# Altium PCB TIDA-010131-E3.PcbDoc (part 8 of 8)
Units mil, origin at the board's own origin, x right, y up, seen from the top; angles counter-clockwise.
Board outline 6889.76 x 5118.11 mil, 6 copper layers (Top Layer, GND Layer, Signal Layer 1, Signal Layer 2, PWR Layer, Bottom Layer), stack 58.5 mil thick; 758 components, 455 nets, 2194 pads, 1156 vias.
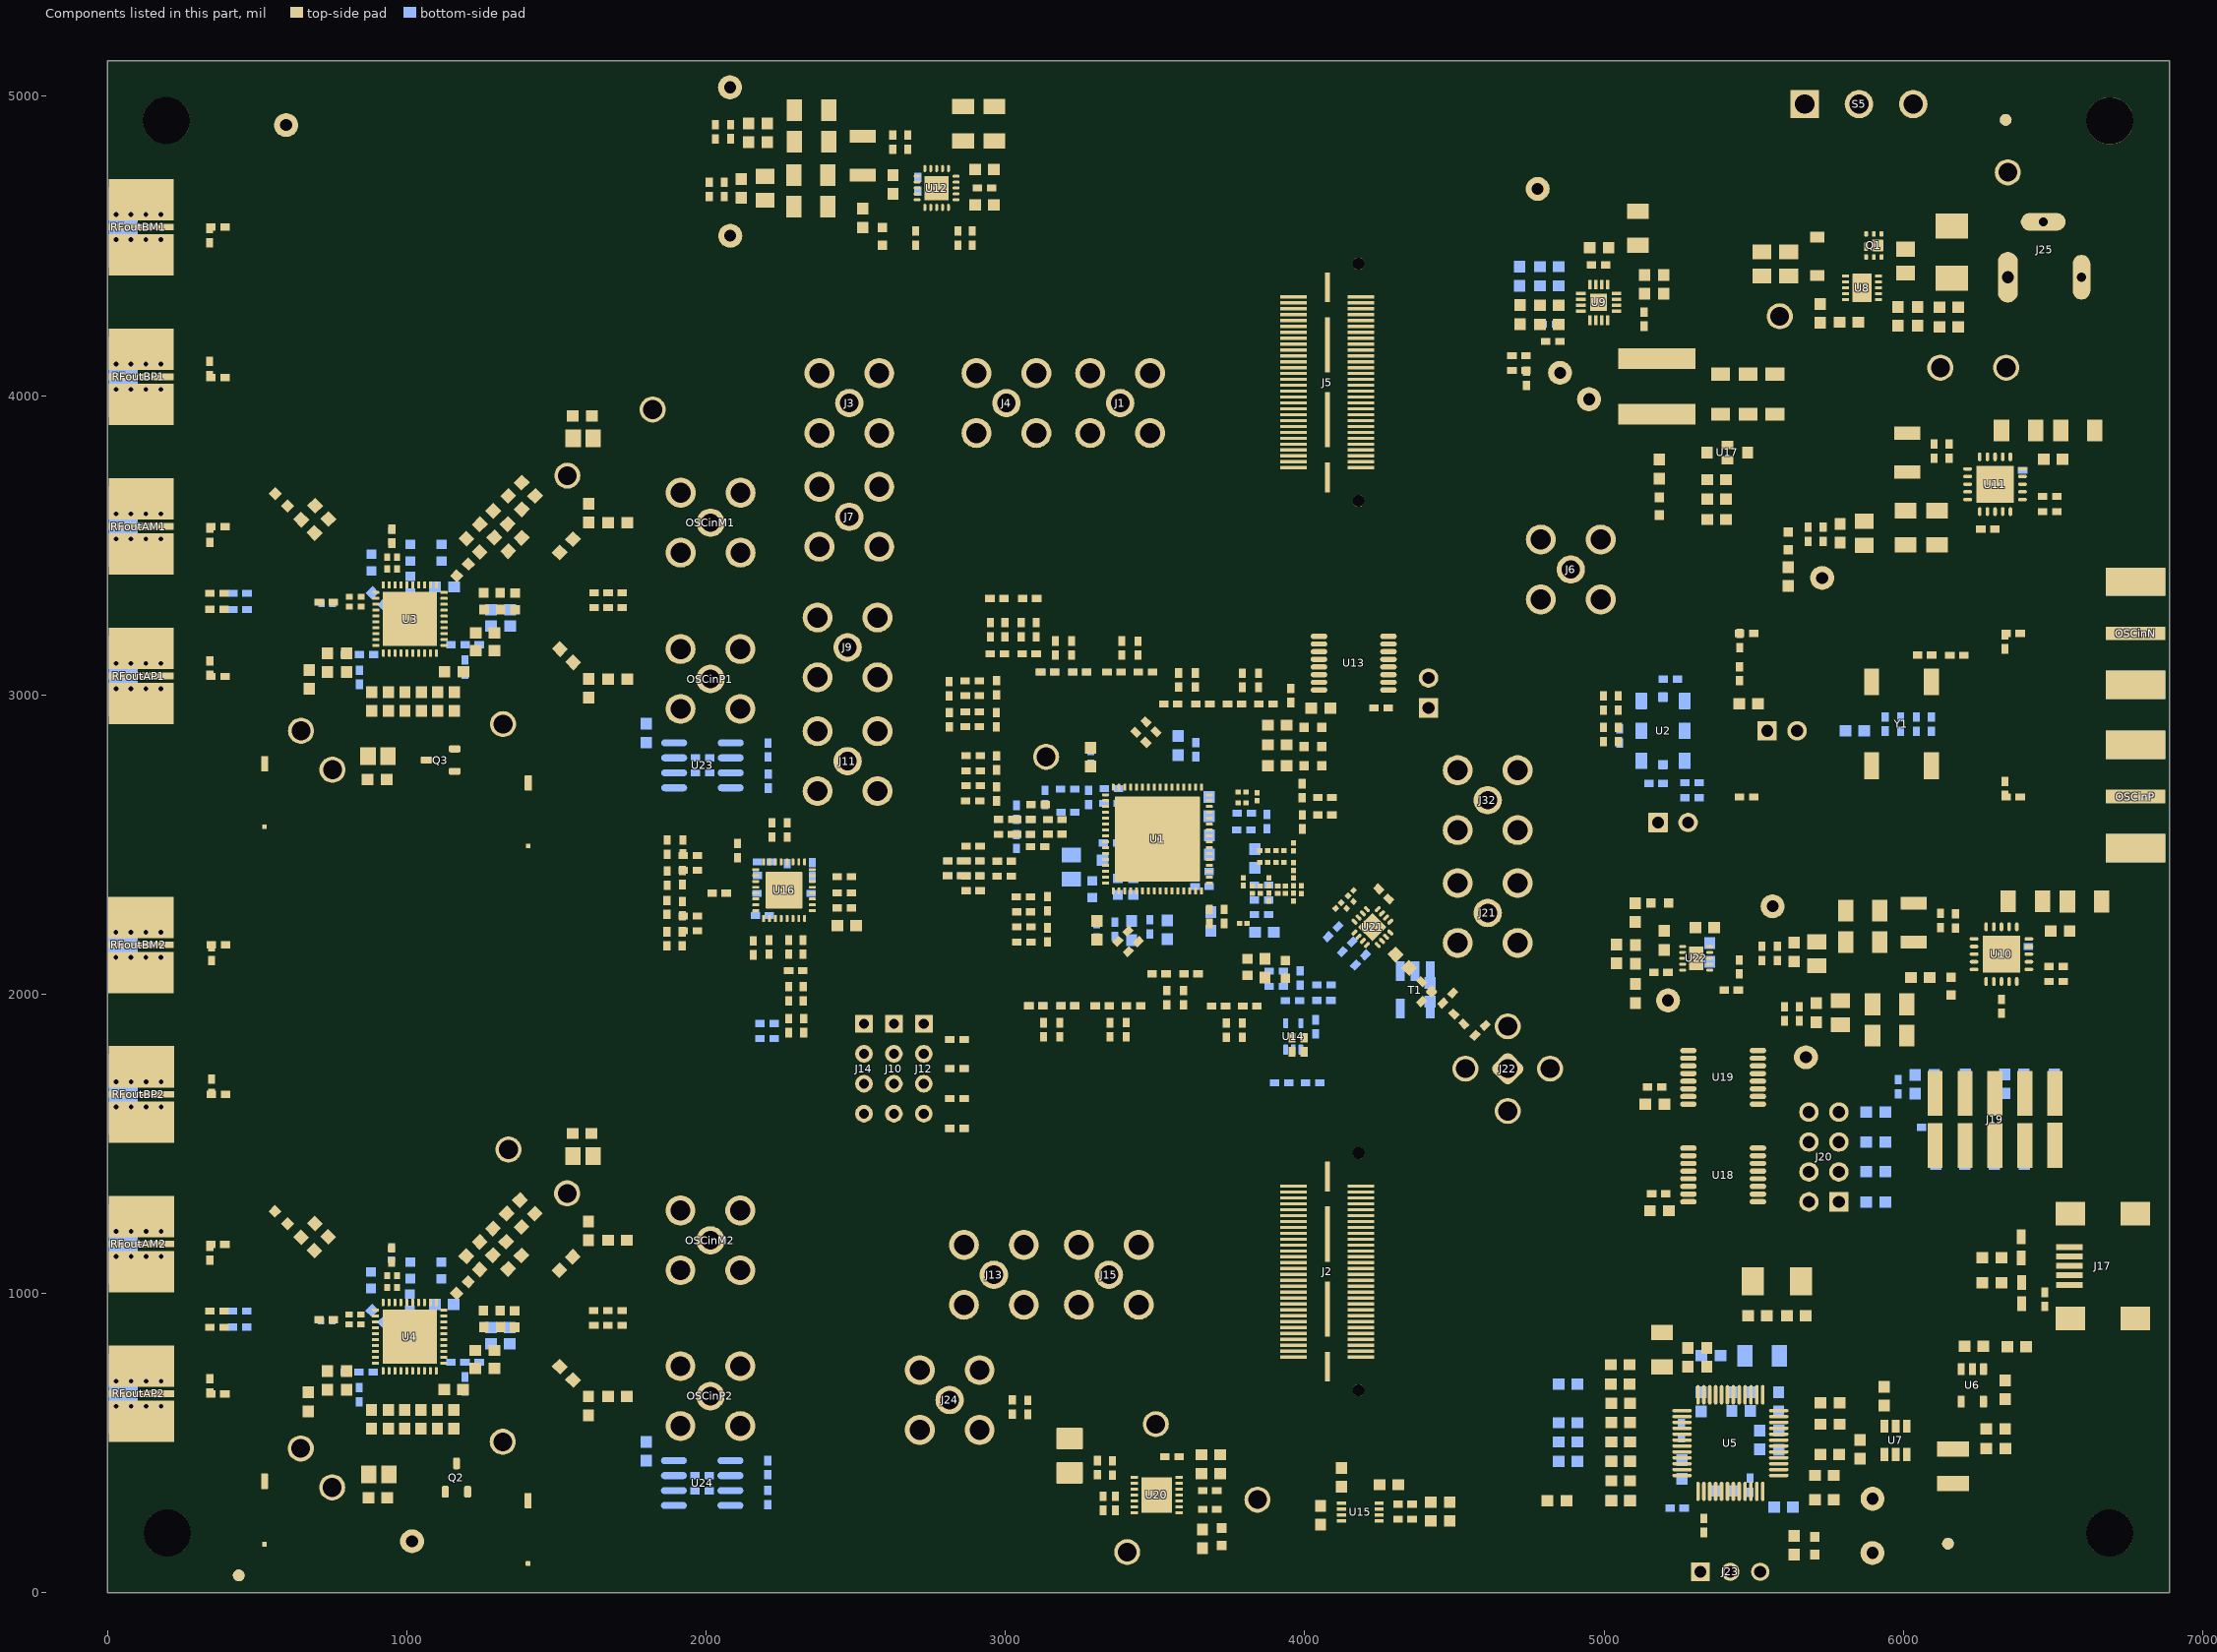
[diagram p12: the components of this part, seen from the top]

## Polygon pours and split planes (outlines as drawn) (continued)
no net on Top Solder "h" (solid): 378.94,634.26 2.41,634.26 -0.76,631.1 -0.76,697.1 6.02,690.32 379.46,690.32 508.41,690.32 619.48,801.39 657.18,839.1 678.24,839.1 695.24,856.1 775.24,856.1 798.24,856.1 828.24,886.1 831.61,889.46 831.61,942.65 808.82,965.43 685.15,965.43 639.96,1010.62 518.63,1131.95 380.29,1131.95 8.39,1131.95 -0.76,1141.1 -0.76,1202.55 6.13,1195.66 379.26,1195.66 539.68,1195.66 677.24,1058.1 712.24,1023.1 753.24,1023.1 785.92,1023.1 853.79,955.24 877.96,931.06 889.26,931.06 895.77,924.54 895.77,899.02 875.61,899.02 860.24,883.65 791.22,814.62 730,814.62 549.65,634.26 378.94,634.26
no net on Top Solder "h" (solid): 368.67,1121.97 368.67,1138.66 363.25,1144.08 296.82,1144.08 306,1134.89 306,1121.97 306,703.27 263.82,661.08 407.82,661.08 368.82,700.08 368.82,729.08 368.82,1124.11
no net on Top Solder "h" (solid): 369.43,3519.87 369.43,3536.57 364.01,3541.98 297.58,3541.98 306.76,3532.79 306.76,3519.87 306.76,3101.17 264.58,3058.98 408.58,3058.98 369.58,3097.98 369.58,3126.98 369.58,3522.01
no net on Top Solder "h" (solid): 379.7,3032.16 3.16,3032.16 0,3029 0,3095 6.77,3088.23 380.22,3088.23 509.17,3088.23 620.23,3199.3 657.94,3237 679,3237 696,3254 776,3254 799,3254 829,3284 832.37,3287.37 832.37,3340.55 809.58,3363.33 685.91,3363.33 640.72,3408.52 519.39,3529.85 381.05,3529.85 9.15,3529.85 0,3539 0,3600.45 6.89,3593.56 380.02,3593.56 540.44,3593.56 678,3456 713,3421 754,3421 786.68,3421 854.54,3353.14 878.72,3328.96 890.01,3328.96 896.53,3322.44 896.53,3296.92 876.37,3296.92 861,3281.55 791.97,3212.52 730.76,3212.52 550.4,3032.16 379.7,3032.16
no net on Top Solder "h" (solid): 368.85,4520.89 368.85,4537.59 363.44,4543 297,4543 306.19,4533.81 306.19,4520.89 306.19,4102.19 264,4060 408,4060 369,4099 369,4128 369,4523.03
no net on Top Solder "h" (solid): 10.56,4014.86 468.56,4014.86 528.82,4075.12 528.82,4356.56 541.31,4369.05 601.47,4369.05 619.48,4351.04 619.48,4095.52 681,4034 833.28,3881.72 833.28,3723.5 833.28,3443.64 872.62,3404.3 914.36,3404.64 934.9,3384.1 934.9,3369.91 969.01,3369.91 969.01,3391.01 982.64,3404.64 1003.74,3404.64 1027.76,3428.66 1056,3456.9 1056,3497.79 1073.04,3514.83 1073.03,4336.97 961,4449 803.88,4606.12 385.16,4606.12 5.67,4606.12 0.33,4600.78 0.33,4537.32 3.65,4534 202,4534 206,4538 298,4538 331,4538 360.82,4501.13 383.06,4523.37 766.14,4523.37 995.34,4294.17 995.34,3451.1 979.11,3434.87 923.38,3434.87 915,3443.25 915,3459 915,3486 909,3492 909,3918 820,4007 700,4127 700,4393 651.14,4441.86 476.89,4441.86 448.49,4413.45 448.49,4369.05 448.49,4112.15 426.17,4089.83 1.83,4089.83 1,4089 1,4045 1,4024.42
VDDD33 on Signal Layer 1 "12" (solid, remove dead copper, pour order 437): 5083,1904 4616,1437 4616,776 4479,639 3203,639 3100,536 3100,82 3147,35 6748,35 6828,115 6828,1702 6795,1735 5990,1735 5821,1904
GND on Signal Layer 1 "PWR Layer-No Net" (solid, remove dead copper, pour order 440): 4459.93,894.93 4254,689 3085,689 3009,613 3009,118 3009,58.5 2985.5,35 63.5,35 13,85.5 13,764 13,5011.5 77,5075.5 4320.5,5075.5 4458.16,4937.85
+3.3V_ALL on Signal Layer 1 "h" (solid, remove dead copper, pour order 411): 4685.5,5024 4615,5024 4546.5,4955.5 4514.5,4923.5 4514.5,4377.5 4514.5,2262.5 4841,1936 5843,1936 6014.5,1764.5 6630,1764.5 6799,1764.5 6831,1796.5 6831,4916 6723.49,5023.51
GND on Bottom Layer "h" (solid, remove dead copper, pour order 445): 282.85,35 63.5,35 25,73.5 25,5023.5 77,5075.5 6717,5075.5 6840.5,4952 6853.85,4938.65 6853.85,4240 6853.85,111 6777.85,35
GND on Bottom Layer "12" (solid, pour order 439): 4221,2266 4182,2227 4182,2222 4222,2182 4230,2182 4268,2220 4268,2229 4231,2266 4221,2266
5V on Bottom Layer "PWR Layer-No Net" (solid, remove dead copper, pour order 435): 5607,5053 5704,5053 5736,5021 5738,5019 5738,4938 5738,4731 6230,4239 6248,4239 6341,4239 6403,4177 6426,4154 6426,4063 6426,4043 6367,3984 6344,3961 6149,3961 6002,3961 5606,4357 5493,4470 5493,4731 5493,4959 5563,5029 5587,5053
NetJ25_1 on Bottom Layer "PWR Layer-No Net" (solid, remove dead copper, pour order 434): 5802,5038 5891,5038 5916,5013 5945,4984 5945,4913 5945,4811 6186,4570 6241,4515 6324,4515 6369,4515 6400,4484 6410,4474 6410,4399 6410,4305 6387,4282 6382,4277 6321,4277 6248,4277 5780,4745 5780,4902 5780,5016
GND on Signal Layer 2 "h" (solid, remove dead copper, pour order 441): 282.85,35 63.5,35 25,73.5 25,5023.5 77,5075.5 6717,5075.5 6840.5,4952 6853.85,4938.65 6853.85,4240 6853.85,111 6777.85,35
+2.5V on Signal Layer 2 "12" (solid, remove dead copper, pour order 438): 5085,2368 5430,2368 5459,2339 5467,2331 5467,2273 5467,1966 5437,1936 5032,1936 4991,1977 4991,2338 5021,2368
GND on GND Layer "h" (solid, remove dead copper, pour order 442): 282.85,35 63.5,35 25,73.5 25,5023.5 77,5075.5 6717,5075.5 6840.5,4952 6853.85,4938.65 6853.85,4240 6853.85,111 6777.85,35

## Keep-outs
Keep-Out Layer:
  lines w10: 6890.89,354.66 6890.89,4685.37 ; 0,0 6889.76,0 6889.76,5118.11 0,5118.11 0,0
  text ".Layer_Name" at -231.37,-1903.49 h60
Multi-Layer:
  circle w6: c4180.64,676.77 r30
  circle w6: c4180.64,1469.29 r30
  circle w6: c4180.64,3648.11 r30
  circle w6: c4180.64,4440.63 r30

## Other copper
Top Layer:
  pour cut-out: 6843.57,3263 6853.85,3252.72 6853.85,3152.85 6844,3143 6670,3143 6664,3149 6664,3258 6669,3263
  pour cut-out: 6843.57,2718 6853.85,2707.72 6853.85,2607.85 6844,2598 6670,2598 6664,2604 6664,2713 6669,2718
  pour cut-out: 4877,4394 4641,4394 4624,4377 4624,4175 4636,4163 4819,4163 4824,4168 4824,4188 4831,4195 4831,4162 4816.29,4147.29 4622.93,4147.29 4604.45,4165.77 4604.45,4385.38 4627.05,4407.99 4890.99,4407.99
  pour cut-out: 5384.39,3833.99 5384.39,3844.39 5393,3853 5394.61,3851.39 5432.61,3851.39 5432.61,3862.27 5371.96,3862.27 5371.96,3858.93 5370.64,3857.61
  region net GND: 4234,2279 4234,2290 4323,2379 4331,2379 4349,2361 4349,2355 4283,2289 4283,2283 4283,2259 4263,2239 4263,2232 4268,2227 4268,2221 4233,2186 4223,2186 4185,2224 4185,2230
  pour cut-out: 1076.07,752.75 1092.25,752.75 1096,749 1096,732 1091.39,727.4 1072.32,727.4 1070,729.72 1070,746.68
  text "TOP LAYER" at -232.15,-1885 h60
GND Layer:
  text "GND Layer" at -205,-1900 h60
Signal Layer 2:
  text "Signal Layer2" at -215,-1900 h60
Signal Layer 1:
  text "Signal Layer1" at -225,-1890 h60
PWR Layer:
  text "PWR Layer" at -195,-1890 h60
Bottom Layer:
  text "BOTTOM LAYER" at -231.37,-1903.49 h60

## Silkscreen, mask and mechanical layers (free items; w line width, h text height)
Top Overlay:
  drawing of 487 lines, arcs and shapes, not listed
  text "+3.3V_LMXRF" at 1694.68,4987.01 h30
  text "GND" at 560.11,4794.49 h30
  text "PGND" at 6455,4709 h30
  text "TIDA-010131-E3" at 3278.18,4651.02 h80
  text "+3.3V_LMX" at 1911.74,4434.15 h30
  text "5VIN" at 5675.09,4093.58 h30 r90
  text "5V" at 6437,4023 h30
  text "EN" at 6016.56,4007.17 h30
  text "B" at 3455,3636 h30
  text "A" at 3096,3619 h30
  text "+3.3V_VCO" at 5788.76,3350 h30
  text "+3.3V_VCO" at 5203.22,2645.43 h30 r90
  text "CLKINN" at 4781.86,2592.14 h30
  text "+3.3V_VCO" at 5573.22,2559.43 h30 r90
  text "A" at 2904,2552 h30
  text "C" at 3762.83,2444.56 h40
  text "B" at 2730,2427 h30
  text "+3.3V_LMK" at 5485.43,2406.78 h30
  text "+2.5v" at 5153,2389 h30
  text "CLKINP" at 4779.47,2205.12 h30
  text "VDD33" at 5618,1688.68 h30
  text "LMK_CLKIN" at 4792,1535 h30 r45
  text "C" at 4393,1443 h40
  text "VDD33" at 5397,139 h30 r90
  text "V_BUS" at 5552,130 h30 r90
  text "VREGIN" at 5445,129 h30 r90
  text "GND" at 873.48,125 h30
  text "GND" at 5977,90 h30
  text "TOP OVERLAY" at -231.37,-1903.49 h50
Bottom Overlay:
  lines w6: 838.89,949.64 849.89,938.64 852.89,938.64 ; 949.65,3440.55 967.65,3458.55 983.65,3458.55 ; 1214.74,687.74 1214.74,698.1 ; 1985.35,276.78 1985.35,307.06 ; 1986.27,229.7 1986.27,251.14 ; 1988.81,2677.47 1988.81,2707.75 ; 1989.73,2630.4 1989.73,2651.84 ; 2095.32,2306.91 2136.32,2306.91 2145.82,2316.41 ; 2112.32,2386.91 2141.32,2386.91 ; 2291.32,2459.91 2297.32,2465.91 ; 2375.82,2316.41 2386.32,2305.91 2388.32,2305.91 ; 2901,2286 2901,2311 ; 2945.72,2554.28 3012.78,2554.28 ; 2946,2605 3008.16,2605 3013.16,2600 ; 3104.58,2713.76 3109.64,2708.71 ; 3200,2834 3200,2790.03 3250,2740.03 3250,2714 ; 3297.17,2469.08 3297.17,2472.3 ; 3407.24,2623.19 3439.39,2623.19 3454.6,2638.4 3454.6,2664.68 ; 3559.97,2374.66 3560.97,2375.66 3560.97,2391.66 3577.97,2408.66 3606.97,2408.66 ; 3708.84,2464.78 3724.85,2464.78 3735.02,2464.78 ; 3799.97,2042.66 3803.76,2046.44 3857.03,2046.44 ; 3800.86,2637.97 3800.86,2660.67 ; 3865.97,1985.66 3866.97,1986.66 3908.97,1986.66 ; 3903.57,2286.28 3939.59,2286.28 ; 3903.57,2335.28 3936.44,2335.28 3940.94,2330.78 ; 4024,1834 4024,1821 4030,1815 ; 4161.74,2206.73 4161.74,2213.74 4167,2219 ; 4886.59,4420.6 4902.29,4404.9 4923.23,4404.9 ; 5392.11,561.18 5392.11,569.24 5399.08,576.22 ; 5516.47,699 5529.5,712.04 ; 5583.06,422.64 5583.06,441.51 ; 5618.18,691.01 5641.55,691.01 ; 5951,1373 5951,1365 5953,1363 5967,1363 ; 5967.98,1478.8 5979.78,1467 5991,1467 ; 6048,1823 6066.27,1804.73 6066.27,1758.98 ; 1985.35,307.06 1992.51,299.9 1977.9,299.9 1985.06,307.06 1985.35,307.06 ; 1986.27,251.14 1993.01,244.4 1980.25,244.4 1986.27,250.43 1986.27,251.14 ; 1988.81,2707.75 1988.51,2707.75 1981.35,2700.6 1995.96,2700.6 1988.81,2707.75 ; 1989.73,2651.84 1989.73,2651.12 1983.71,2645.1 1996.47,2645.1 1989.73,2651.84 ; 2901,2311 2902,2311 2908,2305 2895,2305 2901,2311 ; 3800.86,2660.67 3795.09,2654.91 3794.84,2654.91 3806.62,2654.91 3800.86,2660.67
  text "BOTTOM OVERLAY" at -117.15,-1917 h50
Top Paste:
  text "TOP PASTE" at -231.37,-1903.49 h60
Bottom Paste:
  text "BOTTOM PASTE" at -231.37,-1903.49 h60
Top Solder:
  text "TOP SOLDER" at -231.37,-1903.49 h60
Bottom Solder:
  text "BOTTOM SOLDER" at -231.37,-1903.49 h60
Drill Guide:
  text ".Layer_Name" at -231.37,-1903.49 h60
M1 Board Outline:
  the board outline again, w10
M2 Board Dimensions:
  rectangle: -683.87,-1455.5 -308.87,-1330.5
  rectangle: -808.87,-1330.5 -683.87,-1205.5
  lines w7: -808.87,-1330.5 191.13,-1330.5 ; -683.87,-1455.5 -683.87,-1205.5 ; -558.87,-1455.5 -558.87,-1205.5 ; -308.87,-1455.5 -308.87,-1205.5 ; -58.87,-1455.5 -58.87,-1205.5 ; -808.87,-1455.5 -808.87,-1205.5 191.13,-1205.5 191.13,-1455.5 -808.87,-1455.5
  lines w10: -808.87,-1520.5 -808.87,-1500.5 ; -748.87,-1530.5 -808.87,-1510.5 ; -748.87,-1490.5 -808.87,-1510.5 ; -584.79,-1510.5 -808.87,-1510.5 ; -32.95,-1510.5 191.13,-1510.5 ; 131.13,-1530.5 191.13,-1510.5 ; 131.13,-1490.5 191.13,-1510.5 ; 191.13,-1520.5 191.13,-1500.5
  text "1000 (mil)" at -574.79,-1546.49 h60
M3 3D STEP Top:
  text ".Layer_Name" at -231.37,-1903.49 h60
M4 3D STEP Bottom:
  text ".Layer_Name" at -231.37,-1903.49 h60
M5 Assembly Top:
  circle w10: c6093.33,3037.38 r21.33
  circle w10: c5501.31,3811.99 r14.18
  circle w10: c5544.19,2882.66 r23.65
  circle w10: c2522.41,1903.14 r14.87
  circle w10: c2627.47,1901.66 r14.87
  circle w10: c2725.47,1902.66 r14.87
  circle w10: c4410.97,2960.66 r16.49
  circle w10: c6548.35,1029.45 r11.18
  circle w10: c6753.97,3206.66 r13.42
  circle w10: c6762.97,2655.66 r13.42
  circle w10: c6509,1669 r11.18
  circle w10: c6288,749 r2.83
  circle w6: c1129,317 r8.25
  circle w6: c5119,137 r18.03
  circle w6: c5318,83 r19.92
  circle w6: c5656,4989 r12.65
  lines w6: 1838.32,2288.91 1815.32,2288.91 ; 1838.32,2386.91 1815.32,2386.91 ; 3889,2504 3889,2516 3837,2516 3837,2597 3837,2608 3946,2608 3946,2531 3937,2522 3937,2504 ; 3917,2502 3917,2520 ; 3921,2413 3758,2413 3758,2320 3800,2278 4022,2278 4152,2408 4471,2408 4471,2549 4389,2631 4376,2631 ; 3994,2399 4058,2399 4099,2440 4099,2543 4187,2631 4390,2631 ; 4078,2171 4078,2231 4095,2248 ; 4095,2240 4095,2248 ; 4142,2438 4066,2362 4034,2362 4020,2362 ; 4161,2389 4162,2389 4226,2325 4219,2318 4122,2221 4228,2115 4228,2079 4080,1931 3974,2037 3974,2082 4053,2161 4053,2281 4161.5,2389.5 ; 5239.21,2051.35 5246.56,2044 5255,2044 ; 1815.32,2288.91 1821.32,2282.91 1821.32,2294.91 1815.32,2288.91 ; 1815.32,2386.91 1821.32,2392.91 1821.32,2380.91 1815.32,2386.91 ; 3917,2520 3911,2514 3925,2514 3919,2520 3917,2520 ; 4020,2362 4027,2369 4027,2356 4021,2362 4020,2362 ; 4095,2248 4085,2248 4094,2239 4094,2247 4095,2248 ; 6520.28,945.38 6522.28,943.38 6888.28,943.38 6888.28,1245.38 6520.28,1245.38 6520.28,964.96 6520.28,945.38
  lines w10: -1100.37,-1975.17 5499.63,-1975.17 ; -1100.37,-1771.83 5501.63,-1771.83 ; -1100.37,-1568.5 -1100.37,-2178.5 2904.63,-2178.5 5501.63,-2178.5 5501.63,-1568.5 -1099.87,-1568.5 -1099.87,-2178.5 475.63,-2178.5 ; 1364.63,-2178.5 1364.63,-1568.5 ; 2631.63,-1771.83 2631.63,-1568.5 ; 3471.63,-1771.83 3471.63,-1568.5 ; 4093.63,-2185 4093.63,-1982.17
  text "2" at 4167.79,4327.1 h25
  text "1" at 3968.34,4322.43 h25
  text "59" at 3964.56,3749.53 h25
  text "60" at 4150.43,3749.53 h25
  text "1" at 3963.74,1351.19 h25
  text "2" at 4163.53,1349.9 h25
  text "J24" at 6676.38,1016.28 h25
  text "60" at 4146.04,778.64 h25
  text "59" at 3964.28,774.68 h25
  text "U5" at 5405,481 h25
  text "COMPONENTS MARKED 'DNP' SHOULD NOT BE POPULATED." at 345.13,-1363.5 h25
  text "ASSEMBLY VARIANT:" at 344.63,-1479 h25
  text ".VariantName" at 1380.63,-1479 h25
  text "E3" at 3066.85,-1694 h25
  text "PCB VIEWED FROM TOP SIDE" at -1036.87,-1700.67 h25
  text "BOARD #:" at 1439.63,-1700.67 h25
  text "'.PRJ_Number'" at 1985.13,-1700.67 h25
  text "REV:" at 2829.63,-1700.67 h25
  text "SVN REV:" at 3667.63,-1700.67 h25
  text "010131" at 1760.73,-1895.8 h25
  text "ASSEMBLY TOP" at -225.15,-1898 h25
  text "TID #:" at 1421.89,-1901.13 h25
  text "IGNORE ->" at -1036.87,-1903.49 h25
  text "PLOT NAME =" at -1036.87,-2109.34 h25
  text ".plot_File_Name" at -231.37,-2109.34 h25
  text "GENERATED    :" at 1441.63,-2109.34 h25
  text "'.Print_Date'" at 2311.13,-2109.34 h25
  text "'.Print_Time'" at 3040.13,-2109.34 h25
  text "TEXAS INSTRUMENTS" at 4304.63,-2109.34 h25
M6 Assembly Bottom:
  circle w10: c2094.32,442.14 r10.94
  circle w10: c2099.72,2839.25 r11.5
  circle w10: c3986.13,1797.87 r5.36
  lines w6: 3250,2733 3271,2712 3271,2709 ; 1847.69,2665.26 2128.74,2665.26 2128.74,2863.47 2127.7,2864.51 2024.37,2864.51 1847.69,2864.51 1847.69,2665.26 ; 1848.36,267.88 1848.36,467.13 2025.04,467.13 2128.36,467.13 2129.4,466.09 2129.4,267.88 1848.36,267.88
  lines w10: -1100.87,-1772.33 5501.13,-1772.33 ; -1098.87,-1975.67 5501.13,-1975.67 ; 307.13,-2185.5 307.13,-1982.67 ; 929.13,-1772.33 929.13,-1569 ; 1769.13,-1772.33 1769.13,-1569 ; 3036.13,-2179 3036.13,-1569 ; 3925.13,-2179 5500.63,-2179 5500.63,-1569 -1100.87,-1569 -1100.87,-2179 1496.13,-2179 5501.13,-2179 5501.13,-1569
  text "COMPONENTS MARKED 'DNP' SHOULD NOT BE POPULATED." at 5293.63,-1363 h25
  text ".VariantName" at 4249.63,-1479 h25
  text "ASSEMBLY VARIANT:" at 5288.63,-1479 h25
  text "E3" at 1297.23,-1687.14 h25
  text "SVN REV:" at 733.13,-1701.17 h25
  text "REV:" at 1571.13,-1701.17 h25
  text "'.PRJ_Number'" at 2415.63,-1701.17 h25
  text "BOARD #:" at 2961.13,-1701.17 h25
  text "PCB VIEWED FROM BOTTOM SIDE" at 5437.63,-1701.17 h25
  text "ASSEMBLY BOTTOM" at 4320.69,-1890.28 h25
  text "010131" at 2635.44,-1893.21 h25
  text "TID #:" at 2974.28,-1898.54 h25
  text "IGNORE ->" at 1739.48,-1903.49 h25
  text "LAYER NAME =" at 5364.94,-1902.63 h25
  text "TEXAS INSTRUMENTS" at 96.13,-2109.84 h25
  text "'.Print_Time'" at 1360.63,-2109.84 h25
  text "'.Print_Date'" at 2089.63,-2109.84 h25
  text "GENERATED    :" at 2959.13,-2109.84 h25
  text ".plot_File_Name" at 4632.13,-2109.84 h25
  text "PLOT NAME =" at 5437.63,-2109.84 h25
M9 Title Sheet:
  drawing of 58 lines, arcs and shapes, not listed
  text "1" at -68.53,6991.5 h70
  text "2" at 2427.13,6991.5 h70
  text "3" at 4916.47,6991.5 h70
  text "4" at 7423.14,6991.5 h70
  text "5" at 9922.13,6991.5 h70
  text "6" at 12427.13,6991.5 h70
  text "A" at 16796.85,5852 h70
  text "A" at -1224.87,5848.5 h70
  text "B" at 16796.85,3472 h70
  text "B" at -1224.87,3468.5 h70
  text "C" at 16796.85,1097 h70
  text "C" at -1224.87,1093.5 h70
  text ".PRJ_Title" at 13806.85,-897.33 h70
  text "DESIGNED FOR:" at 13756.85,-1065 h45
  text ".PRJ_Customer" at 13806.85,-1205 h70
  text "D" at 16796.85,-1273 h70
  text "D" at -1224.87,-1276.5 h70
  text "FILE NAME:" at 13756.85,-1365 h45
  text ".PCB_File_Name_No_Path" at 13806.85,-1485 h70
  text "Texas Instruments (TI) and/or its licensors do not warrant the accuracy or completeness of this specification" at 5565.63,-1650.34 h45
  text "ENGINEER:" at 13756.85,-1655 h45
  text "LAYOUT BY:" at 15261.85,-1655 h45
  text "or any information contained therein. TI and/or its licensors do not warrant that this design will meet" at 5520.65,-1763 h45
  text ".PRJ_Engineer" at 13806.85,-1809.99 h70
  text ".PCB_Layout" at 15312.35,-1809.99 h70
  text "the specifications, will be suitable for your application or fit for any particular purpose, or will operate in" at 5520.65,-1875.67 h45
  text "ALTIUM DESIGNER VERSION:" at 15261.85,-1965 h45
  text "an implementation. TI and/or its licensors do not warrant that the design is production worthy. You should" at 5520.65,-1988.33 h45
  text ".print_Scale" at 13806.85,-2098.33 h70
  text ".Application_BuildNumber" at 15312.35,-2098.33 h70
  text "completely validate and test your design implementation to confirm the system functionality for your application." at 5565.63,-2101 h45
  text "1" at -68.53,-2308.5 h70
  text "2" at 2427.13,-2308.5 h70
  text "3" at 4916.47,-2308.5 h70
  text "4" at 7423.14,-2308.5 h70
  text "5" at 9922.13,-2308.5 h70
  text "6" at 12427.13,-2308.5 h70
M10 Fab Notes:
  drawing of 245 lines, arcs and shapes, not listed
  text "DESIGN INFORMATION" at 14794.37,5768.5 h60
  text "(REFER ALSO ARRAY/PANEL PROFILING INFORMATION)" at 14432.81,5606.79 h60
  text "BOARD SIZE" at 13746.81,5602.5 h60
  text "130mm" at 14894.57,5478.5 h60
  text "X" at 14714.81,5474.68 h60
  text "175MM" at 14149.57,5468.5 h60
  text "Number of Layers :" at 14149.81,5277.5 h60
  text "6" at 15244.62,5267.5 h60
  text "MIN. TRACK WIDTH:" at 14149.81,5138.5 h60
  text "MIL" at 15400.81,5138.5 h60
  text "4.25" at 15137.57,5137.5 h60
  text "4.25" at 15122.57,5010.5 h60
  text "MIN. CLEARANCE:" at 14149.81,5006.5 h60
  text "MIL" at 15400.81,5006.5 h60
  text "16" at 15189,4882 h60
  text "MIN. VIA PAD SIZE:" at 14149.81,4874.5 h60
  text "MIL" at 15400.81,4874.5 h60
  text "5.90 MIL" at 14844.81,4732.79 h60
  text "MINIMUM ANNULAR RING" at 13820.58,4728.5 h60
  text "EXTERNAL" at 15657.57,4728.5 h60
  text "PER" at 14020.58,4610.5 h60
  text "IPC-D-275 CLASS 2 LEVEL C" at 14240.58,4610.5 h60
  text "+/-" at 15336.35,4497.5 h60
  text "MIL, HOLES" at 15728.81,4498.21 h60
  text "+/-" at 16190.35,4497.5 h60
  text "5" at 15596.55,4492.5 h60
  text "3" at 16429.55,4492.5 h60
  text "REGISTRATION TOLERANCES:" at 13820.58,4492.5 h60
  text "METAL" at 15020.35,4492.5 h60
  text "MIL" at 16545.81,4492.5 h60
  text "IMPEDANCE TABLE:-" at 7654.85,4374 h60
  text "MATERIAL:" at 13745.81,4283.04 h60
  text "SE IMP" at 8220.85,4206 h50
  text "SE TRACE" at 8617.85,4203 h50
  text "DIFF TRACE" at 9540.85,4203 h50
  text "DIFF IMP" at 9093.85,4202 h50
  text "DIFF IMP" at 10286.85,4202 h50
  text "Rogers4003C and FR4 370" at 15975,4160 h30
  text "FR-4 High Tg" at 14732.25,4142.71 h60
  text "REFERENCE" at 11558.85,4139 h50
  text "X" at 15465,4135 h60
  text "FR-408" at 14166.81,4134.14 h60
  text "OTHER" at 15654.81,4134.14 h60
  text "(OHM)" at 8255.85,4118 h50
  text "(OHM)" at 9128.85,4114 h50
  text "(OHM)" at 10321.85,4114 h50
  text "WIDTH IN" at 8625.85,4108 h50
  text "WIDTH/SPACING" at 9548.85,4108 h50
  text "WIDTH/SPACING" at 10741.85,4108 h50
  text "Layer" at 7752.85,4089 h50
  text "+/-10%" at 8234.85,4034 h50
  text "Layer" at 11641.85,4032 h50
  text "+/-10%" at 9107.85,4030 h50
  text "+/-10%" at 10300.85,4030 h50
  text "MILS" at 8625.85,4021 h50
  text "IN MILS" at 9548.85,4021 h50
  text "IN MILS" at 10741.85,4021 h50
  text "63 MIL (1.6mm) +/-10%" at 14486.91,3971.42 h60
  text "THICKNESS:" at 13820.58,3967.14 h60
  text "X" at 14358.75,3967.14 h60
  text "OTHER" at 15771.81,3967.14 h60
  text "50(CPW)" at 8223.85,3877 h50
  text "22mil" at 8653.85,3875 h50
  text "15mil trace/" at 9581.85,3871 h50
  text "12mil trace/" at 10790.85,3869 h50
  text "GND" at 11640.85,3862 h50
  text "90 ohms" at 9101.85,3827 h50
  text "100 ohms" at 10281.85,3825 h50
  text "Top Layer" at 7702.85,3818 h50
  text "TOLERANCE:" at 13820.58,3809.14 h60
  text "X" at 14659.88,3809.14 h60
  text "ANSI IPC-6012 TYPE 3 CLASS 2" at 14846.83,3809.14 h60
  text "24mil" at 8653.85,3785 h50
  text "7mil space" at 9581.85,3785 h50
  text "Layer" at 11644.85,3784 h50
  text "8mil space" at 10790.85,3783 h50
  text "50" at 8223.85,3781 h50
  text "OTHER +/-" at 14846.81,3653.14 h60
  text "5.5mil trace/" at 10796.85,3648 h50
  text "SIGNAL" at 7769.85,3634 h50
  text "GND" at 11635.85,3623 h50
  text "100 ohms" at 10297.85,3616 h50
  text "90 ohms" at 9105.85,3611 h50
  text "10.5 mil" at 8649.85,3607 h50
  text "50" at 8330.85,3602 h50
  text "-" at 9780,3580 h60
  text "6mil space" at 10796.85,3562 h50
  text "Layer1" at 7782.85,3555 h50
  text "Layer" at 11639.85,3545 h50
  text "BOW & TWIST:" at 13820.58,3496.14 h60
  text "X" at 14659.88,3496.14 h60
  text "ANSI IPC-6012 TYPE 3 CLASS 2" at 14846.83,3496.14 h60
  text "5.5mil trace/" at 10788.85,3415 h50
  text "SIGNAL" at 7769.85,3407 h50
  text "PWR" at 11633.85,3393 h50
  text "10.5 mil" at 8643.85,3379 h50
  text "50" at 8322.85,3377 h50
  text "100 ohms" at 10289.85,3377 h50
  text "90 ohms" at 9095.85,3376 h50
  text "-" at 9780,3365 h60
  text "OTHER +/-" at 14846.81,3337.63 h60
  text "6mil space" at 10788.85,3329 h50
  text "Layer2" at 7782.85,3328 h50
  text "Layer" at 11637.85,3315 h50
  text "COPPER THICKNESS (FINISHED):" at 13745.81,3202.14 h60
  text "BOTTOM" at 7768.85,3181 h50
  text "PWR" at 11638.85,3177 h50
  text "4.25mil trace/" at 10733.85,3172 h50
  text "13.5 mil" at 8649.85,3141 h50
  text "90 ohms" at 9092.85,3126 h50
  text "100 ohms" at 10294.85,3122 h50
  text "-" at 9775,3120 h60
  text "50" at 8333.85,3113 h50
  text "Layer" at 7781.85,3102 h50
  text "Layer" at 11642.85,3099 h50
  text "4.25mil space" at 10733.85,3086 h50
  text "1.4MIL (1oz)" at 14625.81,3049.42 h60
  text "2MIL (1.4oz)" at 15392.81,3049.42 h60
  text "2.8MIL (2oz)" at 16119.81,3049.42 h60
  text "OUTER:" at 14102.81,3045.14 h60
  text "X" at 14497.35,3044.5 h60
  text "X" at 15267.35,2895.5 h60
  text "N/A" at 16119.35,2892.79 h60
  text "1.4MIL (1oz)" at 14625.81,2892.42 h60
  text "0.7MIL (1/2oz)" at 15392.81,2892.42 h60
  text "INNER SIGNAL:" at 13813.73,2888.14 h60
  text "X" at 14497.35,2884.5 h60
  text "22 mil (CPW) width on top layer should be controlled 50 ohms +/- 5%" at 7567,2816 h60
  text "DRILLING:" at 13745.81,2749.14 h60
  text "ALL SMA CONNECTORS TO FLUSH TO THE EDGE OF THE BOARD, NO GAP ALLOWED." at 7635,2687 h60
  text "REFERENCE:" at 13820.58,2632.14 h60
  text "X" at 14468.81,2632.14 h60
  text "AS SHOWN" at 14655.81,2632.14 h60
  text "X" at 15369.81,2632.14 h60
  text "NC_DRILL FILES" at 15506.81,2632.14 h60
  text "This is especially critical for:  RFoutAP, RFoutAM, RFoutBP, and RFoutBM SMA connectors" at 7622,2572 h60
  text "PTH MIN COPPER THICKNESS:" at 13820.58,2474.14 h60
  text "X" at 15170.81,2474.14 h60
  text "1MIL" at 15307.81,2474.14 h60
  text "OTHER" at 15804.81,2474.14 h60
  text "BOARD FINISH:" at 13745.81,2315.14 h60
  text "SILKSCREEN:" at 13901.03,2197.14 h60
  text "X" at 14849.81,2197.14 h60
  text "TOP" at 14975.81,2197.14 h60
  text "X" at 15359.81,2197.14 h60
  text "BOTTOM" at 15486.81,2197.14 h60
  text "SILKSCREEN COLOR:" at 13901.03,2030.14 h60
  text "X" at 14848.77,2030.14 h60
  text "WHITE" at 14975.81,2030.14 h60
  text "OTHER" at 15486.81,2030.14 h60
  text "SOLDER RESIST COLOR:" at 13901.03,1860.14 h60
  text "X" at 15054,1708 h60
  text "GREEN" at 14595.81,1700.94 h60
  text "BLUE" at 15186.81,1700.94 h60
  text "OTHER" at 15724.81,1700.94 h60
  text "IMMERSION GOLD (ENIG)" at 14806.81,1512.42 h60
  text "ENEPIG" at 16144.35,1509.14 h60
  text "SURFACE FINISH:" at 13745.81,1508.14 h60
  text "X" at 14619.86,1508.14 h60
  text "IMM. TIN/SILVER OR EQUIV" at 14075.35,1351.14 h60
  text "OTHER" at 15506.81,1351.14 h60
  text "ARRAY/PANEL:" at 13745.81,1172.14 h60
  text "CUT AND TRIM PER MECH LAYER 1" at 14806.81,1167.85 h60
  text "N.C. ROUTE" at 14806.81,1016.14 h60
  text "X" at 15485.81,1016.14 h60
  text "V. SCORE" at 15672.81,1016.14 h60
  text "CERTIFICATION:" at 13745.81,879.14 h60
  text "MATERIALS AND WORKMANSHIP FOR ALL PCBS" at 14470.81,879.14 h60
  text "TO MEET OR EXCEED THE REQUIREMENTS OF:" at 14470.81,781.14 h60
  text "X" at 14097.31,644.63 h60
  text "ANSI IPC-A-600F CLASS ->" at 14236.31,644.63 h60
  text "X" at 15875.37,644.63 h60
  text "2" at 15994.31,644.64 h60
  text "1" at 15679.31,643.14 h60
  text "3" at 16348.31,643.14 h60
  text "X" at 14099.37,485.14 h60
  text "UL 94V-0" at 14236.31,485.14 h60
  text "X" at 14911.37,485.14 h60
  text "RoHS" at 15048.31,485.14 h60
  text "OTHER" at 15692.71,485.14 h60
  text "PER ORDER" at 16089.77,485.14 h60
  text "ADDITIONAL REQUIREMENTS:" at 13745.81,344.14 h60
  text "VIA TENTING:" at 14963.35,343.5 h60
  text "X" at 16039,342 h60
  text "YES" at 15513.02,334.42 h60
  text "NO" at 15877.82,329.19 h60
  text "MICROSECTION:" at 13820.58,229.14 h60
  text "YES" at 14726.31,229.14 h60
  text "X" at 16189.57,220.5 h60
  text "IMPEDANCE CONTROL:" at 14989.35,219.5 h60
  text "YES" at 15973.35,218.5 h60
  text "NO" at 16348.82,201.19 h60
  text "REQUIRED" at 15587.81,72.99 h60
  text "BARE BOARD ELEC. TEST:" at 13820.58,70.14 h60
  text "NONE" at 15126.31,70.14 h60
  text "X" at 15460.81,70.14 h60
  text "PER ORDER" at 16179.81,70.14 h60
  text "MANUFACTURER'S UL:" at 13820.58,-86.86 h60
  text "RAIL" at 14986.31,-91.15 h60
  text "METAL" at 15478.12,-91.15 h60
  text "SILK" at 15989.81,-91.15 h60
  text "X" at 15853.35,-91.5 h60
M11 Gerber Information:
  lines w10: -1100.37,-1975.17 5499.63,-1975.17 ; -1100.37,-1771.83 5501.63,-1771.83 ; -1100.37,-1568.5 -1100.37,-2178.5 2904.63,-2178.5 5501.63,-2178.5 5501.63,-1568.5 -1099.87,-1568.5 -1099.87,-2178.5 475.63,-2178.5 ; 1364.63,-2178.5 1364.63,-1568.5 ; 2631.63,-1771.83 2631.63,-1568.5 ; 3471.63,-1771.83 3471.63,-1568.5 ; 4093.63,-2185 4093.63,-1982.17
  text "E3" at 3122.85,-1696 h40
  text "ALL ARTWORK VIEWED FROM TOP SIDE" at -1036.87,-1700.67 h60
  text "BOARD #:" at 1439.63,-1700.67 h60
  text "'.PRJ_Number'" at 1985.13,-1700.67 h60
  text "REV:" at 2829.63,-1700.67 h60
  text "SVN REV:" at 3667.63,-1700.67 h60
  text "010131" at 1756.48,-1897.21 h60
  text "LAYER NAME =" at -1036.87,-1903.49 h60
  text "TID #:" at 1417.64,-1902.54 h60
  text "PLOT NAME =" at -1036.87,-2109.34 h60
  text ".plot_File_Name" at -231.37,-2109.34 h60
  text "GENERATED    :" at 1441.63,-2109.34 h60
  text "'.Print_Date'" at 2311.13,-2109.34 h60
  text "'.Print_Time'" at 3040.13,-2109.34 h60
  text "TEXAS INSTRUMENTS" at 4304.63,-2109.34 h60
M12 Stackup:
  drawing of 399 lines, arcs and shapes, not listed
  text "Layer" at 7647.5,6472.5 h60
  text "Name" at 8057.41,6472.5 h60
  text "Material" at 8997.15,6472.5 h60
  text "Thickness" at 9856.92,6472.5 h60
  text "Constant" at 10506.76,6472.5 h60
  text "Board Layer Stack" at 11076.62,6472.5 h60
  text "1" at 7647.5,6352.5 h60
  text "Top Overlay" at 8057.41,6352.5 h60
  text "2" at 7647.5,6232.5 h60
  text "Top Solder" at 8057.41,6232.5 h60
  text "Solder Resist" at 8997.15,6232.5 h60
  text "0.40mil" at 9856.92,6232.5 h60
  text "3.5" at 10506.76,6232.5 h60
  text "3" at 7647.5,6112.5 h60
  text "Top Layer" at 8057.41,6112.5 h60
  text "Copper" at 8997.15,6112.5 h60
  text "1.40mil" at 9856.92,6112.5 h60
  text "4" at 7647.5,5992.5 h60
  text "Dielectric1" at 8057.41,5992.5 h60
  text "Rogers4003C" at 8997.15,5992.5 h60
  text "12.00mil" at 9856.92,5992.5 h60
  text "4.2" at 10506.76,5992.5 h60
  text "5" at 7647.5,5872.5 h60
  text "GND Layer" at 8057.41,5872.5 h60
  text "Copper" at 8997.15,5872.5 h60
  text "0.70mil" at 9856.92,5872.5 h60
  text "6" at 7647.5,5752.5 h60
  text "Dielectric 4" at 8057.41,5752.5 h60
  text "FR4 370" at 8997.15,5752.5 h60
  text "8.50mil" at 9856.92,5752.5 h60
  text "4.2" at 10506.76,5752.5 h60
  text "7" at 7647.5,5632.5 h60
  text "Signal Layer 1" at 8057.41,5632.5 h60
  text "Copper" at 8997.15,5632.5 h60
  text "1.40mil" at 9856.92,5632.5 h60
  text "8" at 7647.5,5512.5 h60
  text "Dielectric 3" at 8057.41,5512.5 h60
  text "FR4 370" at 8997.15,5512.5 h60
  text "14.50mil" at 9856.92,5512.5 h60
  text "4.2" at 10506.76,5512.5 h60
  text "9" at 7647.5,5392.5 h60
  text "Signal Layer 2" at 8057.41,5392.5 h60
  text "Copper" at 8997.15,5392.5 h60
  text "1.40mil" at 9856.92,5392.5 h60
  text "10" at 7647.5,5272.5 h60
  text "Dielectric 5" at 8057.41,5272.5 h60
  text "FR4 370" at 8997.15,5272.5 h60
  text "8.50mil" at 9856.92,5272.5 h60
  text "4.2" at 10506.76,5272.5 h60
  text "11" at 7647.5,5152.5 h60
  text "PWR Layer" at 8057.41,5152.5 h60
  text "Copper" at 8997.15,5152.5 h60
  text "0.70mil" at 9856.92,5152.5 h60
  text "12" at 7647.5,5032.5 h60
  text "Dielectric 2" at 8057.41,5032.5 h60
  text "FR4 370" at 8997.15,5032.5 h60
  text "8.00mil" at 9856.92,5032.5 h60
  text "4.2" at 10506.76,5032.5 h60
  text "13" at 7647.5,4912.5 h60
  text "Bottom Layer" at 8057.41,4912.5 h60
  text "Copper" at 8997.15,4912.5 h60
  text "1.40mil" at 9856.92,4912.5 h60
  text "14" at 7647.5,4792.5 h60
  text "Bottom Solder" at 8057.41,4792.5 h60
  text "Solder Resist" at 8997.15,4792.5 h60
  text "0.40mil" at 9856.92,4792.5 h60
  text "3.5" at 10506.76,4792.5 h60
  text "15" at 7647.5,4672.5 h60
  text "Bottom Overlay" at 8057.41,4672.5 h60
M13 Component Bodies Top:
  text ".Layer_Name" at -231.37,-1903.49 h60
M14 Component Bodies Bottom:
  text ".Layer_Name" at -231.37,-1903.49 h60
M15 Courtyards Top:
  text ".Layer_Name" at -231.37,-1903.49 h60
M16 Courtyards Bottom:
  text ".Layer_Name" at -231.37,-1903.49 h60
Drill Drawing:
  circle w10: c7292.63,32.28 r33.33
  lines w10: 7259.29,148.94 7259.29,165.61 7275.96,182.28 7259.29,198.94 7259.29,215.61 7275.96,215.61 7292.63,198.94 7309.29,215.61 7325.96,215.61 7325.96,198.94 7309.29,182.28 7325.96,165.61 7325.96,148.94 7309.29,148.94 7292.63,165.61 7275.96,148.94 7259.29,148.94 ; 7259.29,298.94 7325.96,298.94 7325.96,365.61 7259.29,365.61 7259.29,298.94 ; 7259.29,665.61 7325.96,665.61 7292.63,598.94 7259.29,665.61 ; 7259.29,782.28 7292.63,748.94 7325.96,782.28 7292.63,815.61 7259.29,782.28 ; 7259.29,915.61 7275.96,915.61 7275.96,898.94 7309.29,898.94 7309.29,915.61 7325.96,915.61 7325.96,948.94 7309.29,948.94 7309.29,965.61 7275.96,965.61 7275.96,948.94 7259.29,948.94 7259.29,915.61 ; 7259.29,1048.94 7325.96,1048.94 7325.96,1115.61 7259.29,1115.61 7259.29,1048.94 ; 7259.29,1215.61 7275.96,1215.61 7275.96,1198.94 7309.29,1198.94 7309.29,1215.61 7325.96,1215.61 7325.96,1248.94 7309.29,1248.94 7309.29,1265.61 7275.96,1265.61 7275.96,1248.94 7259.29,1248.94 7259.29,1215.61 ; 7259.29,1515.61 7275.96,1515.61 7292.63,1498.94 7309.29,1515.61 7325.96,1515.61 7309.29,1532.28 7325.96,1548.94 7309.29,1548.94 7292.63,1565.61 7275.96,1548.94 7259.29,1548.94 7275.96,1532.28 7259.29,1515.61 ; 7259.29,2015.61 7325.96,2015.61 7292.63,1948.94 7259.29,2015.61 ; 7259.29,2098.94 7292.63,2115.61 7325.96,2098.94 7309.29,2132.28 7325.96,2165.61 7292.63,2148.94 7259.29,2165.61 7275.96,2132.28 7259.29,2098.94 ; 7272.63,312.28 7312.63,312.28 7312.63,352.28 7272.63,352.28 7272.63,312.28 ; 7272.63,652.28 7312.63,652.28 7292.63,612.28 7272.63,652.28 ; 7272.63,922.28 7282.63,922.28 7282.63,912.28 7302.63,912.28 7302.63,922.28 7312.63,922.28 7312.63,942.28 7302.63,942.28 7302.63,952.28 7282.63,952.28 7282.63,942.28 7272.63,942.28 7272.63,922.28
  lines w15: 7199.5,-46.06 12574.05,-46.06 ; 7199.5,2353.94 12574.05,2353.94 ; 7750.38,-196.06 7750.38,2503.94 ; 8400.2,-196.06 8400.2,2503.94 ; 9549.86,-196.06 9549.86,2503.94 ; 10055.74,-196.06 10055.74,2503.94 ; 10789.54,-196.06 10789.54,2503.94 ; 11379.39,-196.06 11379.39,2503.94 ; 7199.5,-196.06 12574.05,-196.06 12574.05,2503.94 7199.5,2503.94 7199.5,-196.06
  text "Symbol" at 7289.5,2398.94 h72
  text "Count" at 7795.38,2398.94 h72
  text "Hole Size" at 8445.2,2398.94 h72
  text "Plated" at 9594.86,2398.94 h72
  text "Hole Type" at 10100.74,2398.94 h72
  text "Via/Pad" at 10834.54,2398.94 h72
  text "Hole Length" at 11424.39,2398.94 h72
  text "117" at 7795.38,2248.94 h60
  text "7.87mil (0.200mm)" at 8445.2,2248.94 h60
  text "PTH" at 9594.86,2248.94 h60
  text "Round" at 10100.74,2248.94 h60
  text "Via" at 10834.54,2248.94 h60
  text "-" at 11424.39,2248.94 h60
  text "I" at 7271.52,2238.95 h66.67
  text "2" at 7795.38,2098.94 h60
  text "10.00mil (0.254mm)" at 8445.2,2098.94 h60
  text "PTH" at 9594.86,2098.94 h60
  text "Round" at 10100.74,2098.94 h60
  text "Via" at 10834.54,2098.94 h60
  text "-" at 11424.39,2098.94 h60
  text "726" at 7795.38,1948.94 h60
  text "12.00mil (0.305mm)" at 8445.2,1948.94 h60
  text "PTH" at 9594.86,1948.94 h60
  text "Round" at 10100.74,1948.94 h60
  text "Via" at 10834.54,1948.94 h60
  text "-" at 11424.39,1948.94 h60
  text "375" at 7795.38,1798.94 h60
  text "16.00mil (0.406mm)" at 8445.2,1798.94 h60
  text "PTH" at 9594.86,1798.94 h60
  text "Round" at 10100.74,1798.94 h60
  text "(Mixed)" at 10834.54,1798.94 h60
  text "-" at 11424.39,1798.94 h60
  text "F" at 7260.41,1788.95 h66.67
  text "2" at 7795.38,1648.94 h60
  text "29.92mil (0.760mm)" at 8445.2,1648.94 h60
  text "PTH" at 9594.86,1648.94 h60
  text "Slot" at 10100.74,1648.94 h60
  text "Pad" at 10834.54,1648.94 h60
  text "120.08mil (3.050mm)" at 11424.39,1648.94 h60
  text "L" at 7260.41,1638.95 h66.67
  text "12" at 7795.38,1498.94 h60
  text "33.47mil (0.850mm)" at 8445.2,1498.94 h60
  text "PTH" at 9594.86,1498.94 h60
  text "Round" at 10100.74,1498.94 h60
  text "Pad" at 10834.54,1498.94 h60
  text "-" at 11424.39,1498.94 h60
  text "1" at 7795.38,1348.94 h60
  text "39.76mil (1.010mm)" at 8445.2,1348.94 h60
  text "PTH" at 9594.86,1348.94 h60
  text "Slot" at 10100.74,1348.94 h60
  text "Pad" at 10834.54,1348.94 h60
  text "140.16mil (3.560mm)" at 11424.39,1348.94 h60
  text "K" at 7260.41,1338.95 h66.67
  text "27" at 7795.38,1198.94 h60
  text "40.00mil (1.016mm)" at 8445.2,1198.94 h60
  text "PTH" at 9594.86,1198.94 h60
  text "Round" at 10100.74,1198.94 h60
  text "Pad" at 10834.54,1198.94 h60
  text "-" at 11424.39,1198.94 h60
  text "4" at 7795.38,1048.94 h60
  text "40.16mil (1.020mm)" at 8445.2,1048.94 h60
  text "NPTH" at 9594.86,1048.94 h60
  text "Round" at 10100.74,1048.94 h60
  text "Pad" at 10834.54,1048.94 h60
  text "-" at 11424.39,1048.94 h60
  text "3" at 7795.38,898.94 h60
  text "40.16mil (1.020mm)" at 8445.2,898.94 h60
  text "PTH" at 9594.86,898.94 h60
  text "Round" at 10100.74,898.94 h60
  text "Pad" at 10834.54,898.94 h60
  text "-" at 11424.39,898.94 h60
  text "16" at 7795.38,748.94 h60
  text "62.00mil (1.575mm)" at 8445.2,748.94 h60
  text "PTH" at 9594.86,748.94 h60
  text "Round" at 10100.74,748.94 h60
  text "Pad" at 10834.54,748.94 h60
  text "-" at 11424.39,748.94 h60
  text "5" at 7795.38,598.94 h60
  text "62.99mil (1.600mm)" at 8445.2,598.94 h60
  text "PTH" at 9594.86,598.94 h60
  text "Round" at 10100.74,598.94 h60
  text "Pad" at 10834.54,598.94 h60
  text "-" at 11424.39,598.94 h60
  text "18" at 7795.38,448.94 h60
  text "63.00mil (1.600mm)" at 8445.2,448.94 h60
  text "PTH" at 9594.86,448.94 h60
  text "Round" at 10100.74,448.94 h60
  text "Pad" at 10834.54,448.94 h60
  text "-" at 11424.39,448.94 h60
  text "J" at 7260.41,438.95 h66.67
  text "3" at 7795.38,298.94 h60
  text "64.96mil (1.650mm)" at 8445.2,298.94 h60
  text "PTH" at 9594.86,298.94 h60
  text "Round" at 10100.74,298.94 h60
  text "Pad" at 10834.54,298.94 h60
  text "-" at 11424.39,298.94 h60
  text "64" at 7795.38,148.94 h60
  text "67.00mil (1.702mm)" at 8445.2,148.94 h60
  text "PTH" at 9594.86,148.94 h60
  text "Round" at 10100.74,148.94 h60
  text "Pad" at 10834.54,148.94 h60
  text "-" at 11424.39,148.94 h60
  text "4" at 7795.38,-1.06 h60
  text "157.00mil (3.988mm)" at 8445.2,-1.06 h60
  text "NPTH" at 9594.86,-1.06 h60
  text "Round" at 10100.74,-1.06 h60
  text "Pad" at 10834.54,-1.06 h60
  text "-" at 11424.39,-1.06 h60
  text "1379 Total" at 7795.38,-151.06 h60
  text "Slot definitions :" at 7289.5,-296.03 h60
  text "Routed Path Length" at 8322.19,-296.03 h60
  text "= Calculated from tool start centre position to tool end centre position." at 9424.86,-296.03 h60
  text "Hole Length" at 8322.19,-396.01 h60
  text "= Routed Path Length + Tool Size = Slot length as defined in the PCB layout" at 9014.99,-396.01 h60
  text "Drill Table" at 7550.85,-497 h60
  text "FOR 7.874MIL DRILL +0/-7.874MIL" at 7518.29,-627.4 h60
  text "FOR 10MIL DRILL +0/-10MIL" at 7513.29,-727.4 h60
  text "FOR 12MIL DRILL +0/-12MIL" at 7513.29,-822.4 h60
  text "FOR 16MIL DRILL +0/-16MIL" at 7513.29,-921.66 h60
  text "FOR PTH DRILL +/-3MIL" at 7515.85,-1040 h60
  text "FOR NPTH DRILL +/-2MIL" at 7515.85,-1120 h60
  text "DRILL DRAWING" at -231.37,-1903.49 h60

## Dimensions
0,0 to 6889.76,0 on M2 Board Dimensions
0,0 to 0,5118.11 on M2 Board Dimensions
